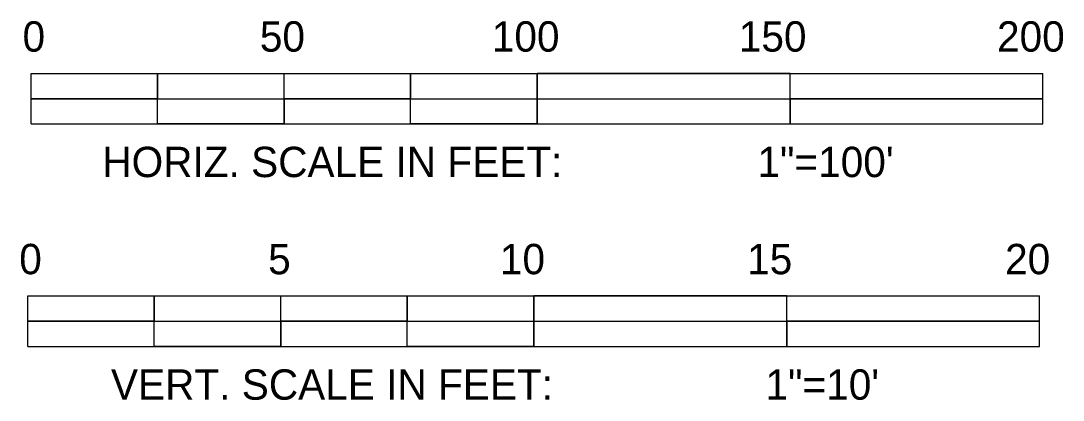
# Model space of a CAD drawing. Extents: x 14.27 to 16.37, y 3.2 to 8.51.
# Drawn here: x 14.295 to 16.355, y 7.755 to 8.505 of the extents above; entities that cross this region are included whole.
import ezdxf

# ---------------------------------------------------------------- set-up
doc = ezdxf.new("R2010")
doc.units = 0
for name, color, linetype in [('R_Border_Scale', 7, 'Continuous'), ('R_Grid', 7, 'Continuous'), ('R_No Plot', 7, 'Continuous')]:
    doc.layers.add(name, color=color, linetype=linetype)

msp = doc.modelspace()

# ---------------------------------------------------------------- linework, layer by layer
at = {"layer": 'R_Border_Scale'}
for p, q in [((14.3153, 8.4012), (16.3153, 8.4012)), ((14.3153, 8.3012), (14.3153, 8.4012)), ((14.3153, 8.4012), (15.3153, 8.4012)), ((14.5653, 8.3012), (14.5653, 8.4012)), ((14.8153, 8.3012), (14.8153, 8.4012)), ((15.0653, 8.3012), (15.0653, 8.4012)), ((15.3153, 8.3012), (15.3153, 8.4012)), ((15.8153, 8.3012), (15.8153, 8.4012)), ((16.3153, 8.3012), (16.3153, 8.4012)), ((14.3153, 8.3512), (16.3153, 8.3512)), ((14.3153, 8.3012), (16.3153, 8.3012))]:
    msp.add_line(p, q, dxfattribs=at)
for points in [[(14.3153, 8.4012), (14.5653, 8.4012), (14.5653, 8.3512), (14.3153, 8.3512)], [(14.8153, 8.4012), (15.0653, 8.4012), (15.0653, 8.3512), (14.8153, 8.3512)], [(15.3153, 8.3512), (15.8153, 8.3512), (15.8153, 8.4012), (15.3153, 8.4012)], [(14.5653, 8.3512), (14.8153, 8.3512), (14.8153, 8.3012), (14.5653, 8.3012)], [(15.0653, 8.3512), (15.3153, 8.3512), (15.3153, 8.3012), (15.0653, 8.3012)], [(15.8153, 8.3012), (16.3153, 8.3012), (16.3153, 8.3512), (15.8153, 8.3512)]]:
    msp.add_lwpolyline(points, close=True, dxfattribs=at)
at = {"layer": 'R_Grid'}
for p, q in [((14.3087, 7.9612), (16.3087, 7.9612)), ((14.3087, 7.8612), (14.3087, 7.9612)), ((14.3087, 7.9612), (15.3087, 7.9612)), ((14.5587, 7.8612), (14.5587, 7.9612)), ((14.8087, 7.8612), (14.8087, 7.9612)), ((15.0587, 7.8612), (15.0587, 7.9612)), ((15.3087, 7.8612), (15.3087, 7.9612)), ((15.8087, 7.8612), (15.8087, 7.9612)), ((16.3087, 7.8612), (16.3087, 7.9612)), ((14.3087, 7.9112), (16.3087, 7.9112)), ((14.3087, 7.8612), (16.3087, 7.8612))]:
    msp.add_line(p, q, dxfattribs=at)
for points in [[(14.3087, 7.9612), (14.5587, 7.9612), (14.5587, 7.9112), (14.3087, 7.9112)], [(14.8087, 7.9612), (15.0587, 7.9612), (15.0587, 7.9112), (14.8087, 7.9112)], [(15.3087, 7.9112), (15.8087, 7.9112), (15.8087, 7.9612), (15.3087, 7.9612)], [(14.5587, 7.9112), (14.8087, 7.9112), (14.8087, 7.8612), (14.5587, 7.8612)], [(15.0587, 7.9112), (15.3087, 7.9112), (15.3087, 7.8612), (15.0587, 7.8612)], [(15.8087, 7.8612), (16.3087, 7.8612), (16.3087, 7.9112), (15.8087, 7.9112)]]:
    msp.add_lwpolyline(points, close=True, dxfattribs=at)
at = {"layer": 'R_No Plot'}
for p, q in [((14.3153, 8.4012), (16.3153, 8.4012)), ((14.3087, 7.9612), (16.3087, 7.9612))]:
    msp.add_line(p, q, dxfattribs=at)

# ---------------------------------------------------------------- texts
at = {"layer": 'R_Border_Scale'}
for s, p in [('0', (14.2983, 8.4442)), ('50', (14.7673, 8.4442)), ('100', (15.2258, 8.4442)), ('150', (15.714, 8.4442)), ('200', (16.2244, 8.4442)), ('HORIZ. SCALE IN FEET:', (14.4559, 8.1962)), ('1"=100\'', (15.7509, 8.1962)), ('0', (14.2918, 8.0042)), ('5', (14.7837, 8.0042)), ('10', (15.2418, 8.0042)), ('15', (15.7305, 8.0042)), ('20', (16.2404, 8.0042)), ('VERT. SCALE IN FEET:', (14.473, 7.7562)), ('1"=10\'', (15.7668, 7.7562))]:
    msp.add_text(s, height=0.06, rotation=360, dxfattribs=at).set_placement(p)

doc.saveas('drawing.dxf')
